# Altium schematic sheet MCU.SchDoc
size A3; SheetNumber: 2; SheetTotal: 9
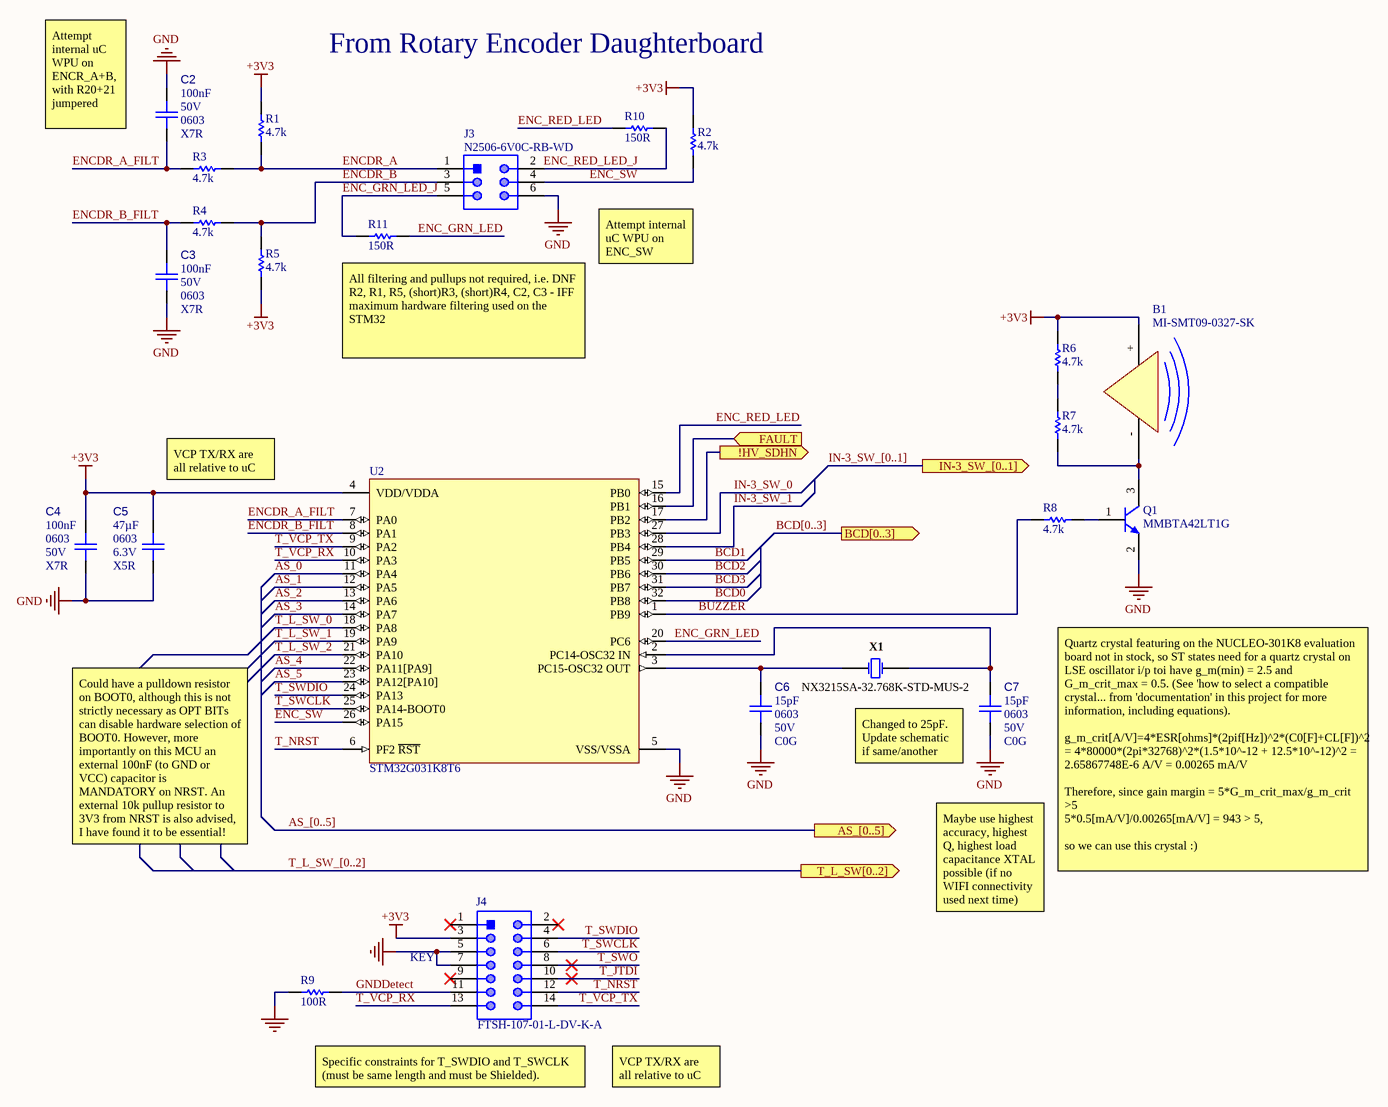
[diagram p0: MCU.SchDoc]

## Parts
?  (no value)
B1  MI-SMT09-0327-SK  [INDP9696X53N]
C2  value 100nF  Voltage Rating: 50V  Case/Package: 0603  Dielectric: X7R  [CAPC1608X09N]  (hidden comment: CGA3E2X7R1H104K080AA)
C3  value 100nF  Voltage Rating: 50V  Case/Package: 0603  Dielectric: X7R  [CAPC1608X09N]  (hidden comment: CGA3E2X7R1H104K080AA)
C4  value 100nF  Voltage Rating: 50V  Case/Package: 0603  Dielectric: X7R  [CAPC1608X09N]  (hidden comment: CGA3E2X7R1H104K080AA)
C5  value 47µF  Dielectric: X5R  Voltage Rating: 6.3V  Case/Package: 0603  [CAPC1608X87X35NL15T15]  (hidden comment: 06036D476MAT2A)
C6  value 15pF  Voltage Rating: 50V  Dielectric: C0G  Case/Package: 0603  [CAPC1608X87X35NL15T15]  (hidden comment: C0603X150J5GACTU)
C7  value 15pF  Voltage Rating: 50V  Dielectric: C0G  Case/Package: 0603  [CAPC1608X87X35NL15T15]  (hidden comment: C0603X150J5GACTU)
J3  N2506-6V0C-RB-WD  [N2506-6V0C-RB-WD-Footprint-1]
J4  FTSH-107-01-L-DV-K-A  [FP-FTSH-107-01-L-DV-K-A-MFG]
Q1  MMBTA42LT1G  [ONSC-SOT-23-3-318-08_V]
R1  value 4.7k  [RESC1608X55X25NL10T15]  (hidden comment: Resistor 4k7 +/-1% 0603 100 mW)
R2  value 4.7k  [RESC1608X55X25NL10T15]  (hidden comment: Resistor 4k7 +/-1% 0603 100 mW)
R3  value 4.7k  [RESC1608X55X25NL10T15]  (hidden comment: Resistor 4k7 +/-1% 0603 100 mW)
R4  value 4.7k  [RESC1608X55X25NL10T15]  (hidden comment: Resistor 4k7 +/-1% 0603 100 mW)
R5  value 4.7k  [RESC1608X55X25NL10T15]  (hidden comment: Resistor 4k7 +/-1% 0603 100 mW)
R6  value 4.7k  [RESC1608X55X25NL10T15]  (hidden comment: Resistor 4k7 +/-1% 0603 100 mW)
R7  value 4.7k  [RESC1608X55X25NL10T15]  (hidden comment: Resistor 4k7 +/-1% 0603 100 mW)
R8  value 4.7k  [RESC1608X55X25NL10T15]  (hidden comment: Resistor 4k7 +/-1% 0603 100 mW)
R9  value 100R  [RESC1608X55X25NL10T15]  (hidden comment: ERJ-3EKF1000V)
R10  value 150R  [RESC1608X55X25NL10T15]  (hidden comment: CRCW0603150RFKEAHP)
R11  value 150R  [RESC1608X55X25NL10T15]  (hidden comment: CRCW0603150RFKEAHP)
U2  STM32G031K8T6  [TQFP80P900X900X160-32N]
X1  NX3215SA-32.768K-STD-MUS-2  [NX3215SA-32.768K-STD-MUS-2-Footprint-1]

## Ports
!HV_SDHN (out), AS_[0..5] (out), BCD[0..3] (out), FAULT (in), IN-3_SW_[0..1] (out), T_L_SW[0..2] (out)

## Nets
+3V3: B1.+(VCC) C4.1 C5.1 J4.3 R1.2 R2.2 R5.1 R6.2 U2.4(VDD/VDDA)
GND: C2.2 C3.1 C4.2 C5.2 C6.2 C7.2 J3.6 J4.5 J4.7 Q1.2(E) R9.1 U2.5(VSS/VSSA)
!HV_SDHN: U2.17(PB2) ; port !HV_SDHN
AS_0: U2.11(PA4)
AS_1: U2.12(PA5)
AS_2: U2.13(PA6)
AS_3: U2.14(PA7)
AS_4: U2.22(PA11[PA9])
AS_5: U2.23(PA12[PA10])
BCD0: U2.32(PB8)
BCD1: U2.29(PB5)
BCD2: U2.30(PB6)
BCD3: U2.31(PB7)
BUZZER: R8.1 U2.1(PB9)
ENC_GRN_LED: R11.2 U2.20(PC6)
ENC_GRN_LED_J: J3.5 R11.1
ENC_RED_LED: R10.2 U2.15(PB0)
ENC_RED_LED_J: J3.2 R10.1
ENC_SW: J3.4 R2.1 U2.26(PA15)
ENCDR_A: J3.1 R1.1 R3.2
ENCDR_A_FILT: C2.1 R3.1 U2.7(PA0)
ENCDR_B: J3.3 R4.2 R5.2
ENCDR_B_FILT: C3.2 R4.1 U2.8(PA1)
FAULT: U2.16(PB1) ; port FAULT
GNDDetect: J4.11 R9.2
IN-3_SW_0: U2.27(PB3)
IN-3_SW_1: U2.28(PB4)
T_JTDI: J4.10
T_L_SW_0: U2.18(PA8)
T_L_SW_1: U2.19(PA9)
T_L_SW_2: U2.21(PA10)
T_NRST: J4.12 U2.6(PF2_~{RST})
T_SWCLK: J4.6 U2.25(PA14-BOOT0)
T_SWDIO: J4.4 U2.24(PA13)
T_SWO: J4.8
T_VCP_RX: J4.13 U2.10(PA3)
T_VCP_TX: J4.14 U2.9(PA2)
NetB1_-: B1.-(GND) Q1.3(C) R7.1
NetC6_1: C6.1 U2.3(PC15-OSC32_OUT) X1.1
NetC7_1: C7.1 U2.2(PC14-OSC32_IN) X1.2
NetQ1_1: Q1.1(B) R8.2
NetR6_1: R6.1 R7.2

Not connected (* = marked no-connect by the designer): J4 1* 2* 9*

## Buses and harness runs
bus AS_[0..5] = port AS_[0..5]
bus BCD[0..3] = port BCD[0..3]
bus IN-3_SW_[0..1] = port IN-3_SW_[0..1]
bus T_L_SW_[0..2] = port T_L_SW[0..2]

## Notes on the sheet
- From Rotary Encoder Daughterboard
- (near C2) Attempt internal uC WPU on ENCR_A+B, with R20+21 jumpered
- Attempt internal uC WPU on ENC_SW
- (near R11) All filtering and pullups not required, i.e. DNF R2, R1, R5, (short)R3, (short)R4, C2, C3 - IFF maximum hardware filtering used on the STM32
- VCP TX/RX are all relative to uC
- Changed to 25pF. Update schematic if same/another 12.5pF load capacitance XTAL is used
- Could have a pulldown resistor on BOOT0, although this is not strictly necessary as OPT BITs can disable hardware selection of BOOT0. However, more importantly on this MCU an external 100nF (to GND or VCC) capacitor is MANDATORY on NRST. An external 10k pullup resistor to 3V3 from NRST is also advised, I have found it to be essential!
- Maybe use highest accuracy, highest Q, highest load capacitance XTAL possible (if no WIFI connectivity used next time)
- Quartz crystal featuring on the NUCLEO-301K8 evaluation board not in stock, so ST states need for a quartz crystal on LSE oscillator i/p toi have g_m(min) = 2.5 and G_m_crit_max = 0.5. (See 'how to select a compatible crystal... from 'documentation' in this project for more information, including equations).
  g_m_crit[A/V]=4*ESR[ohms]*(2pif[Hz])^2*(C0[F]+CL[F])^2 = 4*80000*(2pi*32768)^2*(1.5*10^-12 + 12.5*10^-12)^2 = 2.65867748E-6 A/V = 0.00265 mA/V
  Therefore, since gain margin = 5*G_m_crit_max/g_m_crit >5
  5*0.5[mA/V]/0.00265[mA/V] = 943 > 5,
  so we can use this crystal :)
- (near J4) KEY
- Specific constraints for T_SWDIO and T_SWCLK (must be same length and must be Shielded).

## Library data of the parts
? = CMP-00003-4: The KETS Schematic Sheet Title Block
B1 = CMP-00030-00004-2: Magnetic Indicator SMT 9.6MM 3V
C2-C4 = CMP-001-00101-1: Ceramic Capacitor, Multilayer, Ceramic, 50V, 10% +Tol, 10% -Tol, X7R, 15% TC, 0.1uF, Surface Mount, 0603; Reference Standard: AEC-Q200; Multilayer: Yes
C5 = CMP-00388-1: 0603 (1608Metric) CERAMIC CAPACITOR ceramic capacitor 6.3V 47uF ±20% X5R; Capacitor Type: MLCC
C6 C7 = CMP-00385-1: Cap Ceramic 15pF 50V C0G 5% Pad SMD 0603 Flexible Termination 125C Extreme Low ESR T/R
J3 = CMP-002-00208-1: 80001386988 N2506-6V0C-Rb-Wd=06//Ht/Vsmt/30U/Rohs/Cap/T&r; Number of Positions: 6; Current Rating: 5A; Pitch: 2.54mm; Connector Type: Male Pin; Insulation Resistance: 1GΩ; Plating Thickness: 762nm; Row Spacing: 6.86mm
J4 = CMP-002-00203-1: Conn Unshrouded Header HDR 14 POS 1.27mm Solder ST Top Entry SMD TIGER CLAW™ Tube; Manufacturer Lifecycle Status: PRODUCTION; Current Rating: 3.4A; Gender: Male; Number of Contacts: 14
Q1 = CMP-013-00062-1: Bipolar (BJT) Single Transistor, General Purpose, NPN, 300 V, 500 mA, 225 mW, SOT-23, Surface Mount; Manufacturer Lifecycle Status: ACTIVE; Frequency: 50MHz; Max Collector Current: 500mA; Collector Emitter Breakdown Voltage: 300V; Emitter Base Voltage (VEBO): 6V; Collector Emitter Saturation Voltage: 500mV; Number of Elements: 1; Max Power Dissipation: 300mW; hFE Min: 40
R1-R8 = CMP-009-00031-13: Chip Resistor, 4.7 KOhm, +/- 1%, 0.1 W, -55 to 155 degC, 0603 (1608 Metric); Power: 100mW
R9 = CMP-00265-1: Fixed Resistor, Metal Glaze/thick Film, 0.1W, 100ohm, 75V, 1% +/-Tol, 100ppm/Cel, Surface Mount, 0603; Package Length: 1.6mm; Package Height: 0.45mm; Power: 100mW; Temperature Coefficient (ppm/Cel): 100; Package Width: 0.8mm; Reference Standard: AEC-Q200; Rated Temperature: 70°C
R10 R11 = CMP-00382-2: Res Thick Film 0603 150 Ohm 1% 1/3W ±100ppm/°C Molded SMD SMD Paper T/R; Voltage Rating: 75V; Power Rating: 330mW; Max Power Dissipation: 250mW; Power: 100mW
U2 = CMP-00383-2: RISC Microcontroller, 32-Bit, FLASH, CORTEX-M0 CPU, 64MHz, CMOS, PQFP32; Supply Voltage Max: 3.6V; Min Supply Voltage: 1.7V; Flash Memory Size: 64kB; EEPROM Memory Size: 0B; Number of A/D Converters: 1; Clock Frequency: 48MHz; Number of USART Channels: 2; Data Memory: 8K; Program Memory: 64K; Peripherals: POR; RAM Size: 8kB; Number of I/Os: 3; Operating Supply Voltage: 1.8V; ADC Channels (Resolution): 16-Ch 12-Bit; Number of Timers/Counters: 9; Number of PWM Channels: 17; Max Junction Temperature (Tj): 105°C; Data Bus Width: 32b; Register Bit Depth: 32; Max Supply Current: 6.9mA; Core Architecture: ARM Cortex-M0+; Interface: I2C, I2S, IrDA, LIN, SMBus, SPI, UART, USART; Number of ADC Channels: 16
X1 = CMP-003-00032-2: Crystal 0.032768MHz ±20ppm (Tol) 12.5pF FUND 80000Ohm Automotive AEC-Q200 2-Pin SMD; ESR (Equivalent Series Resistance): 80kΩ; ESR: 80k; Frequency Tolerance: 0.002%; Frequency: 32.768kHz; Frequency Stability: 400ppm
